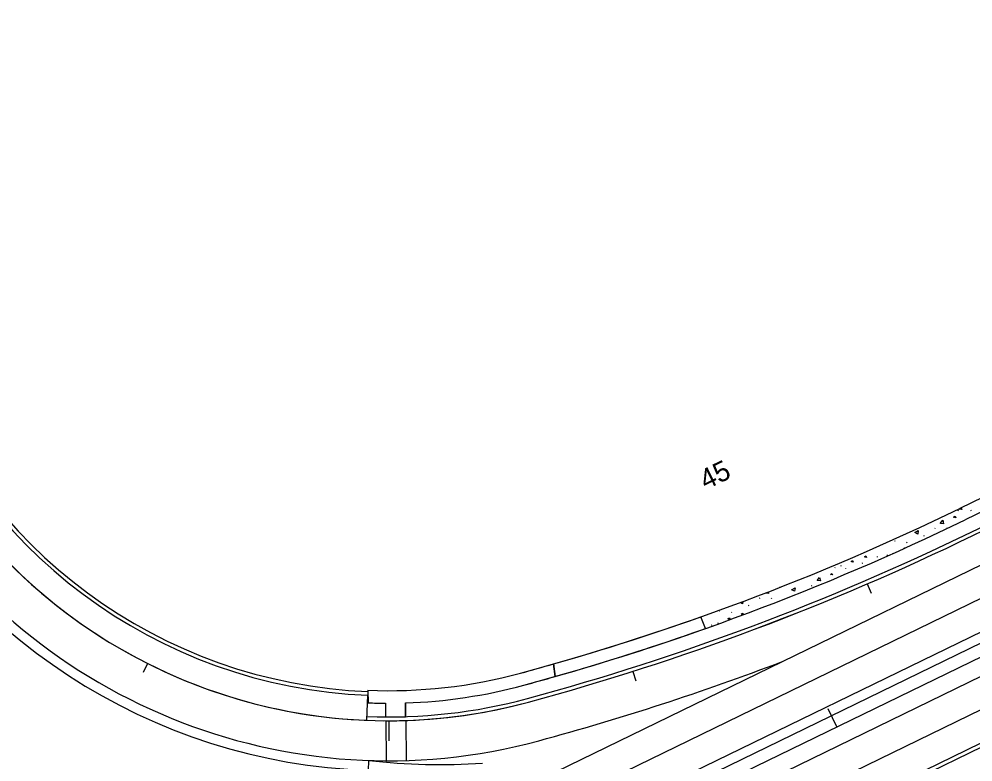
# Model space of a CAD drawing. Extents: x 2339272 to 2351734, y 366540 to 375057.
# Drawn here: x 2348627 to 2349008.3, y 367828.8 to 368125.8 of the extents above; entities that cross this region are included whole.
import ezdxf

# ---------------------------------------------------------------- set-up
doc = ezdxf.new("R2010")
doc.units = 0
for name, color, linetype in [('RD_HC_Cl', 7, 'Continuous'), ('RD_HC_CL_Rel', 7, 'Continuous'), ('RD_HC_Data_Tic', 7, 'Continuous'), ('RD_HC_Data_Tic_Rel', 7, 'Continuous'), ('RD_HC_TX_Sta50', 7, 'Continuous'), ('RD_PD_Final_LnLine', 7, 'Continuous'), ('RD_PD_Final_TrvlWay', 7, 'Continuous'), ('RD_PD_FOC', 7, 'Continuous'), ('RD_PD_PaveShd', 7, 'Continuous'), ('RD_PD_SW', 7, 'Continuous')]:
    doc.layers.add(name, color=color, linetype=linetype)

msp = doc.modelspace()

# ---------------------------------------------------------------- linework, layer by layer
at = {"layer": 'RD_HC_Cl'}
msp.add_line((2348794.11, 367765.14), (2349441.47, 368080.05), dxfattribs=at)
at = {"layer": 'RD_HC_CL_Rel'}
for centre, radius, start, end in [((2348774.65, 368059.29), 214.01, 62.9734, 174.0669), ((2348774.63, 368059.29), 213.99, 174.0669, 285.1604), ((2348566.46, 368827.6), 1010, 285.16043, 295.94073)]:
    msp.add_arc(centre, radius, start, end, dxfattribs=at)
at = {"layer": 'RD_HC_Data_Tic'}
msp.add_line((2348953.92, 367842.88), (2348950.42, 367850.07), dxfattribs=at)
at = {"layer": 'RD_HC_Data_Tic_Rel'}
for p, q in [((2348965.99, 367899.98), (2348967.57, 367896.31)), ((2348678.35, 367868.18), (2348676.55, 367864.61)), ((2348872.34, 367865.03), (2348873.55, 367861.22)), ((2348774.77, 367845.3), (2348774.77, 367837.3))]:
    msp.add_line(p, q, dxfattribs=at)
at = {"layer": 'RD_PD_Final_LnLine'}
for p, q in [((2348932.13, 367868.98), (2349312.02, 368053.77)), ((2348784.92, 367784.02), (2349317.27, 368042.98)), ((2348790.17, 367773.23), (2349322.52, 368032.19)), ((2348791.92, 367769.63), (2349276.99, 368005.6)), ((2348797.17, 367758.84), (2349282.24, 367994.81)), ((2348802.42, 367748.05), (2349287.49, 367984.01)), ((2348773.54, 367845.31), (2348773.68, 367829.31)), ((2348781.54, 367845.42), (2348781.68, 367829.41))]:
    msp.add_line(p, q, dxfattribs=at)
at = {"layer": 'RD_PD_Final_TrvlWay'}
for p, q in [((2349008.27, 367919.36), (2349341.05, 368081.24)), ((2348969.53, 367816), (2349130.88, 367894.48)), ((2348779.67, 367794.81), (2348932.13, 367868.98))]:
    msp.add_line(p, q, dxfattribs=at)
for centre, radius, start, end in [((2348774.64, 368059.31), 230, 61.0108, 285.1623), ((2348774.64, 368059.31), 214, 61.0108, 285.1604), ((2348566.46, 368827.6), 1010, 285.16118, 295.94073), ((2348566.46, 368827.6), 1026, 285.16158, 290.87974), ((2348795.32, 368069.44), 241.69, 263.2226, 274.0094)]:
    msp.add_arc(centre, radius, start, end, dxfattribs=at)
at = {"layer": 'RD_PD_FOC'}
for p, q in [((2349007.62, 367920.71), (2349240.94, 368034.21)), ((2348970.19, 367814.65), (2349131.53, 367893.14))]:
    msp.add_line(p, q, dxfattribs=at)
for centre, radius, start, end in [((2348774.64, 368059.31), 202.5, 62.9734, 267.6766), ((2348566.46, 368827.6), 1008.5, 285.16118, 295.94073), ((2348774.64, 368059.31), 212.5, 267.6974, 285.1604)]:
    msp.add_arc(centre, radius, start, end, dxfattribs=at)
at = {"layer": 'RD_PD_PaveShd'}
for p, q in [((2348766.05, 367845.48), (2348766.45, 367855.47)), ((2348766.63, 367829.45), (2348766.49, 367825.45))]:
    msp.add_line(p, q, dxfattribs=at)
for radius, start, end in [(234, 81.2484, 268.0036), (204, 61.0108, 267.6974)]:
    msp.add_arc((2348774.64, 368059.31), radius, start, end, dxfattribs=at)
at = {"layer": 'RD_PD_SW'}
for p, q in [((2349389.83, 368118.81), (2349003.02, 367930.15)), ((2349392.39, 368114.49), (2349005.21, 367925.65)), ((2349002.33, 367929.28), (2349002.56, 367929.44)), ((2349007.48, 367929.32), (2349007.71, 367929.48)), ((2348993.03, 367922.13), (2348993.25, 367922.29)), ((2348997.82, 367922.21), (2348997.76, 367922.1)), ((2348988.69, 367919.25), (2348988.92, 367919.41)), ((2348977.02, 367917.2), (2348976.91, 367916.97)), ((2348981.8, 367916.48), (2348982.03, 367916.64)), ((2348969.96, 367910.93), (2348969.97, 367910.73)), ((2348973.87, 367911.42), (2348974.09, 367911.57)), ((2348976.33, 367912.34), (2348976.34, 367912.19)), ((2348953.07, 367906.4), (2348953.29, 367906.56)), ((2348955.53, 367907.33), (2348955.54, 367907.13)), ((2348957.31, 367906.19), (2348957.32, 367905.99)), ((2348964.04, 367908.33), (2348964.27, 367908.48)), ((2348943.24, 367903.31), (2348943.47, 367903.47)), ((2348949.16, 367905.91), (2348949.17, 367905.72)), ((2348943.76, 367899.25), (2348943.99, 367899.41)), ((2348918.63, 367891.35), (2348918.85, 367891.51)), ((2348922.97, 367894.24), (2348923.19, 367894.39)), ((2348927.75, 367894.31), (2348927.65, 367894.09)), ((2348906.96, 367889.3), (2348906.85, 367889.07)), ((2348911.74, 367888.58), (2348911.96, 367888.74)), ((2348901.35, 367882.16), (2348899.47, 367886.8)), ((2348903.81, 367883.52), (2348904.03, 367883.67)), ((2348906.27, 367884.44), (2348906.28, 367884.24)), ((2348841.3, 367862.99), (2348840.6, 367867.99)), ((2348840.6, 367867.99), (2348841.3, 367862.99)), ((2348766.43, 367857.47), (2348766.47, 367852.47)), ((2348773.48, 367852.31), (2348773.52, 367846.85)), ((2348773.48, 367852.31), (2348773.52, 367846.85)), ((2348781.47, 367852.42), (2348781.52, 367846.92)), ((2348781.52, 367846.92), (2348781.47, 367852.42))]:
    msp.add_line(p, q, dxfattribs=at)
for points in [[(2349003, 367929.93), (2349003.64, 367930.36), (2349003.9, 367929.72), (2349003, 367929.93)], [(2348995.26, 367924.22), (2348996.26, 367925.46), (2348996.59, 367924.07), (2348995.29, 367924.21)], [(2349000.56, 367926.69), (2349001.2, 367927.11), (2349001.46, 367926.47), (2349000.56, 367926.69)], [(2348985.09, 367920.53), (2348986.46, 367921.36), (2348986.29, 367919.94), (2348985.11, 367920.51)], [(2348980.55, 367914.08), (2348981, 367914.37), (2348981.03, 367914.3)], [(2348964.89, 367910.81), (2348965.53, 367911.24), (2348965.79, 367910.6), (2348964.89, 367910.81)], [(2348959.56, 367908.93), (2348960.2, 367909.36), (2348960.46, 367908.72), (2348959.56, 367908.93)], [(2348946, 367901.33), (2348947, 367902.58), (2348947.33, 367901.19), (2348946.02, 367901.33)], [(2348951.3, 367903.81), (2348951.94, 367904.23), (2348952.2, 367903.59), (2348951.3, 367903.81)], [(2348931.34, 367898.72), (2348931.4, 367898.57), (2348931.13, 367898.64)], [(2348935.83, 367897.65), (2348937.2, 367898.48), (2348937.03, 367897.06), (2348935.85, 367897.63)], [(2348926.39, 367896.77), (2348926.53, 367896.18), (2348925.23, 367896.31)], [(2348916.34, 367892.96), (2348916.23, 367892.04), (2348915.21, 367892.54)], [(2348915.62, 367887.93), (2348916.26, 367888.35), (2348916.53, 367887.71), (2348915.62, 367887.93)], [(2348910.3, 367886.05), (2348910.94, 367886.48), (2348911.2, 367885.83), (2348910.3, 367886.05)], [(2348827.47, 367864.34), (2348827.47, 367864.34)], [(2348766.43, 367857.47), (2348766.43, 367856.97), (2348766.45, 367855.47), (2348766.47, 367852.47)], [(2348828.78, 367859.51), (2348828.78, 367859.51)], [(2348773.52, 367846.85), (2348773.52, 367846.81)]]:
    msp.add_lwpolyline(points, dxfattribs=at)
for centre, radius, start, end in [((2348566.46, 368827.6), 998, 285.16118, 295.94073), ((2348566.46, 368827.6), 1003, 285.16118, 295.94073), ((2348566.46, 368827.6), 998, 285.94365, 289.49196), ((2348566.46, 368827.6), 1003, 285.90336, 289.50479), ((2348566.46, 368827.6), 998, 285.16118, 285.94365), ((2348774.64, 368059.31), 202, 267.6696, 285.1604), ((2348774.64, 368059.31), 202, 267.6696, 285.1604), ((2348566.46, 368827.6), 1003, 285.16118, 285.90336), ((2348774.64, 368059.31), 207, 271.8912, 285.1604), ((2348774.64, 368059.31), 207, 271.8912, 285.1604), ((2348566.46, 368827.6), 1003, 285.16117883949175, 285.16118119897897), ((2348774.64, 368059.31), 207, 285.1604031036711, 285.1604169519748), ((2348566.46, 368827.6), 1003, 285.16117598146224, 285.16117883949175), ((2348774.64, 368059.31), 207, 285.1604169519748, 285.16042838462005), ((2348774.64, 368059.31), 207, 267.7382, 269.6767), ((2348774.64, 368059.31), 207, 267.7382, 269.6767), ((2348774.64, 368059.31), 212.5, 269.6981, 271.8554)]:
    msp.add_arc(centre, radius, start, end, dxfattribs=at)

# ---------------------------------------------------------------- texts
at = {"layer": 'RD_HC_TX_Sta50'}
msp.add_text('45', height=8, rotation=25.9407, dxfattribs=at).set_placement((2348901.49, 367937.48))

doc.saveas('drawing.dxf')
